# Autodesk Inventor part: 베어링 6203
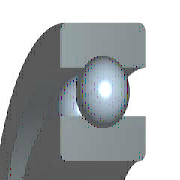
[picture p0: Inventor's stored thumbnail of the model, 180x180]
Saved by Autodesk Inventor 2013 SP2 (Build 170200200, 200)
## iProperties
IsCustomPart: 0
Created: 2014-10
Part Number: 베어링 6203
Material: 강철, 연강
Description: 깊은 그루브 볼 베어링
Document SubType Name: Modeling
Standard: KS B 2023
Designer: KYOUNG IL JANG
Standards Organization: KS
Language: ko-KR
Size Designation: 6203 - 17 x 40 x 12
Categories: <MemberInstance><Categories><Category DisplayName="샤프트 부품" InternalName="7f7aeb1f-a693-4053-b835-cee3144e0d98" Mnemonic="SHFT"><Category DisplayName="베어링" Inter
Density: 7.86 g/cm^3
Mass: 64.9809 g
Surface Area: 64.3582 cm^2
Volume: 8.26729 cm^3
Author: SeoGD™ [www.esajin.kr]
Revision Number: 1
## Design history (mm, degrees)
sketch "스케치" dims "d0" = 5.98 (= -0.26 x WD + 0.26 x BD)
  geometry: L1 (3.01, 14.25)-(8.99, 14.25); L2 (6, 14.25)-(6, 11.26); L3 (6, 14.25)-(6, 17.24); L4 (3.778, 12.249)-(0, 12.249); L5 (0, 8.5)-(12, 8.5); L6 (3.778, 16.251)-(0, 16.251); L7 (0, 20)-(12, 20); L8 (12, 8.5)-(12, 12.249); L9 (8.222, 12.249)-(12, 12.249); L10 (8.222, 16.251)-(12, 16.251); L11 (12, 20)-(12, 16.251); L12 (-1.4, 0)-(8.4, 0) reference; L13 (0, -0.3)-(0, 5.3) reference
  constraints: 22 end point, 4 point on line, 2 collinear, 2 perpendicular, 2 symmetric about line, 1 midpoint, 1 parallel, 14 other
  dimensions: "d9" = 17 diameter of L5 L12 (= WD); "d11" = 40 diameter of L7 L12 (= BD); "d12" = 12 distance between parallel lines of L8 L13 (= KB); "d13" = 24.498 diameter of L9 L12 (= 0.326 x BD + 0.674 x WD)
revolve "본체" stored, may be unused: angle "d6" = 90 deg
revolve "볼" stored, may be unused: angle "d7" = 90 deg
pattern_circular "IDS_ARRAYBALL[SIMPL:T]" dims angle "d3" = 360 deg
body "Solid1"
fillet "모깎기1" dims "d1" = 0.6 (= KRS)
other parameters: "WD" = 17 [user parameter; used in 5 equation terms], "BD" = 40 [user parameter; used in 5 equation terms], "KB" = 12 [user parameter; used in 1 equation term], "KRS" = 0.6 [user parameter; used in 1 equation term], "d4" = 0, "d5" = 0, "d8" = 0, "d14" = 0, "d15" = 0, "BBA" = 0 [user parameter], "BC0" = 4750000 [user parameter], "BC" = 9560000 [user parameter], "WR" = 8.5 (= 0.5 x WD) [user parameter]
